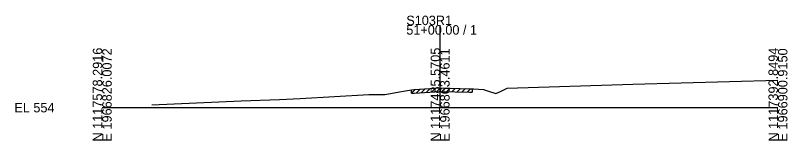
# Model space of a CAD drawing. Extents: x -26 to 203, y -10 to 12018.
# Drawn here: x -25.7 to 202.8, y -9.7 to 27.2 of the extents above; entities that cross this region are included whole.
import ezdxf

# ---------------------------------------------------------------- set-up
doc = ezdxf.new("R2010")
doc.units = 0
for name, color, linetype in [('Level 60', 7, 'Continuous'), ('Level 61', 7, 'Continuous'), ('Level 63', 7, 'Continuous')]:
    doc.layers.add(name, color=color, linetype=linetype)

msp = doc.modelspace()

# ---------------------------------------------------------------- linework, layer by layer
at = {"layer": 'Level 60'}
for p, q in [((119.86, 5.71), (157.06, 6.89)), ((157.06, 6.89), (200, 8.11)), ((83.61, 3.91), (88.61, 4.78)), ((88.61, 4.78), (89.19, 4.87)), ((89.19, 4.87), (91.52, 5.26)), ((91.52, 5.26), (92.32, 5.31)), ((92.32, 5.31), (100.02, 5.81)), ((100.02, 5.81), (108.8, 5.56)), ((108.8, 5.56), (109.51, 5.54)), ((109.51, 5.54), (109.92, 5.51)), ((109.92, 5.51), (112.85, 5.32)), ((112.85, 5.32), (114.34, 4.91)), ((114.34, 4.91), (116.47, 4.2)), ((116.47, 4.2), (117.92, 4.77)), ((117.92, 4.77), (119.86, 5.71)), ((41.15, 1.99), (52.51, 2.36)), ((52.51, 2.36), (58.55, 2.7)), ((58.55, 2.7), (78.89, 3.85)), ((78.89, 3.85), (82.97, 3.9)), ((82.97, 3.9), (83.61, 3.91)), ((14.64, 0.84), (41.15, 1.99))]:
    msp.add_line(p, q, dxfattribs=at)
at = {"layer": 'Level 61'}
for p, q in [((91.52, 4.26), (92.59, 5.33)), ((91.52, 4.26), (91.52, 5.26)), ((92.32, 4.31), (100.02, 4.81)), ((93.02, 4.36), (94.09, 5.43)), ((94.52, 4.45), (95.59, 5.52)), ((96.02, 4.55), (97.09, 5.62)), ((97.52, 4.65), (98.59, 5.72)), ((99.02, 4.75), (100.08, 5.81)), ((100.02, 4.81), (108.8, 4.56)), ((100.52, 4.8), (101.49, 5.77)), ((102.02, 4.75), (102.99, 5.73)), ((103.52, 4.71), (104.49, 5.68)), ((105.02, 4.67), (105.99, 5.64)), ((106.52, 4.62), (107.49, 5.6)), ((108.02, 4.58), (108.99, 5.55)), ((109.51, 5.54), (109.51, 4.54)), ((91.52, 4.26), (92.32, 4.31)), ((108.8, 4.56), (109.51, 4.54))]:
    msp.add_line(p, q, dxfattribs=at)
at = {"layer": 'Level 63'}
for p, q in [((100, 0), (100, 24.34)), ((0, 0), (100, 0)), ((100, 0), (200, 0))]:
    msp.add_line(p, q, dxfattribs=at)

# ---------------------------------------------------------------- texts
for s, p in [('S103R1', (90, 24.34)), ('51+00.00 / 1', (90, 21.54)), ('EL 554', (-26, -1.4))]:
    msp.add_text(s, height=2.8, dxfattribs=at).set_placement(p)
for s, p in [('N 1117578.2916', (0, -10)), ('E 1966826.0072', (2.8, -10)), ('N 1117485.5705', (100, -10)), ('E 1966863.4611', (102.8, -10)), ('N 1117392.8494', (200, -10)), ('E 1966900.9150', (202.8, -10))]:
    msp.add_text(s, height=2.8, rotation=90, dxfattribs=at).set_placement(p)

doc.saveas('drawing.dxf')
